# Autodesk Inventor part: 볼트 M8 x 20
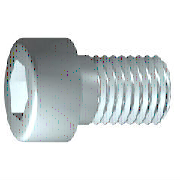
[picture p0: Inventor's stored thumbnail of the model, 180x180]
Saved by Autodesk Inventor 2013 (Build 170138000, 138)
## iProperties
IsCustomPart: 1
Created: 2012-02
Part Number: 볼트 M8 x 20
Material: 강철, 연강
Description: 원통형 머리 캡 나사
Document SubType Name: Modeling
Standard: JIS B 1176
Designer: mdu-01
Standards Organization: JIS
Language: ko-KR
Size Designation: M8 x 20
Categories: <MemberInstance><Categories><Category DisplayName="조임쇠" InternalName="e4da775c-781d-43d5-af7c-5136215cf5a6" Mnemonic="FSTN"><Category DisplayName="볼트" InternalN
Density: 1 g/cm^3
Author: mdu-01
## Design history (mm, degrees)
sketch "스케치1"
  geometry: L1 (-2, 0)-(20, 0); L2 (20, 0)-(20, 4); L3 (20, 4)-(3.125, 4); L4 (3.125, 4)-(2.358, 4); L5 (2.358, 4)-(0, 4); L6 (0, 4)-(0, 6.5); L7 (0, 6.5)-(-8, 6.5); L8 (-8, 6.5)-(-8, 3.464); L9 (-8, 3.464)-(-4, 3.464); L10 (-4, 3.464)-(-2, 0); L11 (-13.6, 0)-(25.6, 0) reference; L12 (0, -1.3)-(0, 7.8) reference; L13 (3.125, 4)-(0, 4)
  constraints: 22 end point, 6 parallel, 2 collinear, 2 perpendicular, 1 horizontal, 1 point on line
  dimensions: "d1" = 16.875 distance from line of L3.end L2 (= GEL); "d2" = 0.76691 distance of L4.end L3.end (computed from GAL); "d3" = 8 distance between parallel lines of L8 L6 (= KOH); "d4" = 4 distance of L8.end L9.end (= INTI); "d5" = 60 deg angle of L10 L1; "d6" = 8 diameter of L3 L1 (= GD); "d7" = 8 diameter of L5 L1 (= BDM); "d8" = 6.9282 diameter of L9 L1 (= 1.1547 x SW); "d9" = 13 diameter of L7 L1 (= KOD); "d26" = 20 distance between parallel lines of L12 L2 (= NLG)
revolve "본체" sketch "스케치1" stored, may be unused: angle "d10" = 90 deg
sketch "스케치2"
  geometry: L1 (0, -9.1)-(0, 9.1) reference; L2 (-9.1, 0)-(9.1, 0) reference; L3 (3.464, 0)-(1.732, -3); L4 (1.732, -3)-(-1.732, -3); L5 (-1.732, -3)-(-3.464, 0); L6 (-3.464, 0)-(-1.732, 3); L7 (-1.732, 3)-(1.732, 3); L8 (1.732, 3)-(3.464, 0); 2 further points
  constraints: 12 end point, 1 coincident, 1 horizontal alignment, 1 point on line, 12 other
extrude "슬롯" join sketch "스케치2" stored distance "d11" = 10; taper "d12" = 0 deg
workplane "Work Plane1"
fillet "Fillet2" dims "d30" = 0.1 (= R)
body "Solid1"
fillet "모깎기1" dims "d17" = 0.8 (= RR)
feature "스레드" dims "d13" = 16.875 (= GEL), "d14" = 0
chamfer "모따기1" distance "d15" = 0.76681 (= -0.5 x SPD + 0.5 x GD); stored, may be unused: second distance "d16" = 0.76681 (= GUL), angle "d27" = 45 deg
other parameters: "GD" = 8 (= NND) [user parameter; used in 2 equation terms], "NLG" = 20 [user parameter; used in 1 equation term], "GEL" = 16.875 [user parameter; used in 2 equation terms], "KOD" = 13 [user parameter; used in 1 equation term], "KOH" = 8 [user parameter; used in 1 equation term], "INTI" = 4 [user parameter; used in 1 equation term], "GAL" = 0.76681 (= 0.61345 x PTC) [user parameter; used in 1 equation term], "GUL" = 0.76681 (= 0.61345 x PTC) [user parameter; used in 1 equation term], "BDM" = 8 (= NND) [user parameter; used in 1 equation term], "SW" = 6 [user parameter; used in 2 equation terms], "RR" = 0.8 [user parameter; used in 1 equation term], "SPD" = 6.46637 (= NND - 1.2269 x PTC) [user parameter; used in 1 equation term], "d19" = 0, "d28" = 0, "d29" = 0, "R" = 0.1 [user parameter; used in 1 equation term], "PHH" = 0.4 [user parameter], "GD1" = 6.46637 (= THREADDIA - 1.2269 x PTC) [user parameter], "THREADDIA" = 8 [user parameter; used in 1 equation term], "FAWI" = 45 deg [user parameter], "TPU" = 8 (computed from PTC) [user parameter], "PTC" = 1.25 [user parameter; used in 5 equation terms], "NND" = 8 [user parameter; used in 3 equation terms], "TOA" = 30 deg [user parameter], "E0" = 6.93 (= 1.155 x SW) [user parameter]
